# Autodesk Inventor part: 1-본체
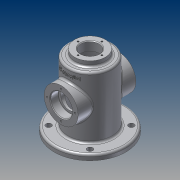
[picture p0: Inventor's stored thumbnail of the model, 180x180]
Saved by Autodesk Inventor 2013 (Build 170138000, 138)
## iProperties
Created: 2014-12
Part Number: 1-본체
Material: 알루미늄 6061
Document SubType Name: Modeling
Designer: CAD-B16
Mass: 479.544 g
Surface Area: 607.62 cm^2
Volume: 176.954 cm^3
Density: 2.71 g/cm^3
Author: CAD-B16
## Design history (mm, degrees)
sketch "스케치1"
  geometry: L1 (0, 45)-(0, -45); L2 (0, 45)-(32.5, 45); L3 (32.5, 45)-(32.5, -45); L4 (32.5, -45)-(0, -45); 2 further points
  constraints: 8 end point, 3 perpendicular, 1 coincident, 1 midpoint, 1 vertical
  dimensions: "d0" = 90 distance of L1.start L1.end; "d2" = 65 diameter of L3 L1
revolve "회전1" sketch "스케치1" stored, may be unused: angle "d3" = 90 deg
feature "쉘1" dims "d4" = 5
sketch "스케치2"
  geometry: C1 r 52.5 at (0, 0); C2 r 27.5 at (0, 0) reference; 1 further point
  constraints: 1 centre point, 1 coincident
  dimensions: "d5" = 105 diameter of C1
extrude "돌출1" join sketch "스케치2" distance "d7" = 8; taper "d8" = 0 deg
node "작업 평면1"
sketch "스케치3"
  geometry: C1 r 22.5 at (0, 0); 1 further point
  constraints: 1 centre point, 1 coincident
  dimensions: "d10" = 45 diameter of C1
extrude "돌출2" join sketch "스케치3" stored distance "d11" = 8; taper "d12" = 0 deg
hole "구멍1" diameter "d15" = 27; stored, may be unused: countersink angle "d19" = 90 deg, drill point angle "d21" = 0 deg; dims "d13" = 10, "d14" = 10, "d16" = 6, "d17" = 4, "d18" = 2, "d20" = 8
sketch "스케치4"
  geometry: 2 further points
  dimensions: "d22" = 17.5 distance of point (0, 0) point (0, 17.5)
hole "구멍2" sketch "스케치4" at (0, 17.5) diameter "d23" = 2.459; stored, may be unused: countersink angle "d27" = 90 deg, drill point angle "d29" = 118 deg; dims "d24" = 6, "d25" = 4, "d26" = 2, "d28" = 8
sketch "스케치5"
  geometry: L1 (0, 0)-(30.406, 30.406); L2 (0, 0)-(43, 0); C1 r 4 at (30.406, 30.406)
  constraints: 4 end point, 1 centre point, 1 coincident, 1 equal length, 1 horizontal
  dimensions: "d33" = 43 distance of L1.start L1.end; "d34" = 45 deg angle of L2 L1; "d35" = 8 diameter of C1
extrude "돌출3" cut sketch "스케치5" stored distance "d36" = 8; taper "d37" = 0 deg
node "작업 평면2"
sketch "스케치6"
  geometry: L1 (-53, 52.5)-(-53, -52.5) reference; C1 r 25 at (2, 0)
  constraints: 1 centre point
  dimensions: "d78" = 55 distance from line of L1 C1.centre
extrude "돌출4" join sketch "스케치6" stored distance "d43" = 8; taper "d44" = 0 deg
sketch "스케치7"
  geometry: C1 r 25 at (0, 0) reference; 2 further points
  dimensions: "d79" = 20.5 distance of C1.centre point (0, 20.5)
hole "구멍3" sketch "스케치7" at (0, 20.5) diameter "d46" = 2.459; stored, may be unused: countersink angle "d50" = 90 deg, drill point angle "d52" = 118 deg; dims "d47" = 6, "d48" = 4, "d49" = 2, "d51" = 8
hole "구멍4" diameter "d58" = 25; stored, may be unused: countersink angle "d62" = 90 deg, drill point angle "d64" = 0 deg; dims "d56" = 10, "d57" = 10, "d59" = 6, "d60" = 32, "d61" = 12, "d63" = 8
node "작업 평면3"
chamfer "모따기1" distance "d69" = 1; stored, may be unused: second distance "d70" = 2, angle "d71" = 45 deg
fillet "모깎기1" dims "d72" = 3
fillet "모깎기2" dims "d73" = 0.3
node "작업 평면4"
sketch "스케치9"
  geometry: L1 (45, 29.5)-(45, -29.5) reference; 2 further points
  constraints: 1 horizontal alignment, 1 other
  dimensions: "d75" = 9 distance from line of L1 point (36, 0)
feature "엠보싱2" sketch "스케치9" dims "d0" = 90, "d2" = 65, "d11" = 8, "d12" = 0, "d76" = 1, "d77" = 0
node "솔리드1"
pattern_circular "원형 패턴1" dims angle "d31" = 360 deg
pattern_circular "원형 패턴2" dims angle "d39" = 360 deg
pattern_circular "원형 패턴3" dims angle "d54" = 360 deg
mirror "대칭1"
other parameters: "d9" = -106, "d41" = 42.5, "d65" = 32.5, "d74" = 32.5
